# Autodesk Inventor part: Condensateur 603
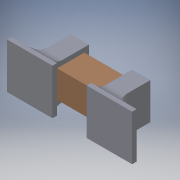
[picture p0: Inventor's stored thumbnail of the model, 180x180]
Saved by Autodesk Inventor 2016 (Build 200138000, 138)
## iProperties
Created: 2018-03
Part Number: Condensateur 603
Material: Générique
Document SubType Name: Modeling
Designer: Bruno
Density: 1 g/cm^3
Appearance: Par défaut
Author: Bruno
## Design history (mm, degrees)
feature "Composite1"
body "Srf1"
